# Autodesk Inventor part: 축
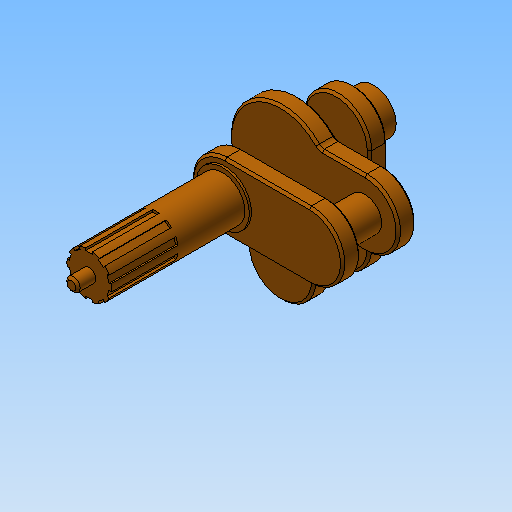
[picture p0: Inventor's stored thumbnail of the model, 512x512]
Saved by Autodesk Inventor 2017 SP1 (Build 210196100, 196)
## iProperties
Created: 2017-05
Part Number: 축
Material: 강철, 연강
Document SubType Name: Modeling
Designer: mduedu
Density: 7.86 g/cm^3
Mass: 656.198 g
Surface Area: 242.498 cm^2
Volume: 83.4857 cm^3
Appearance: 주황색
Author: mduedu
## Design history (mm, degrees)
sketch "스케치1"
  geometry: L1 (-38, 15)-(-17.436, 15); L2 (-38, -15)-(-17.436, -15); L3 (-15, -38)-(-15, -17.436); L4 (15, -38)-(15, -17.436); A1 r 23 centre (0, 0) between (-17.436, 15) and (-17.436, -15); A2 r 15 centre (-38, 0) between (-38, 15) and (-38, -15); A3 r 15 centre (0, -38) between (-15, -38) and (15, -38); 1 further point
  constraints: 8 end point, 8 point on circle, 4 tangent, 3 centre point, 2 horizontal, 2 vertical, 1 coincident, 1 horizontal alignment, 1 vertical alignment
  dimensions: "d0" = 46 diameter of A1; "d1" = 30 diameter of A2; "d2" = 30 diameter of A3 (= d1); "d3" = 38 distance of point (0, 0) A2.centre; "d4" = 38 distance of A3.centre point (0, 0)
extrude "돌출1" new body sketch "스케치1" distance "d5" = 8; taper "d6" = 0 deg
fillet "모깎기1" dims "d7" = 3
sketch "스케치2"
  geometry: C1 r 7.5 at (0, -38); A1 r 15 centre (0, -38) between (-15, -38) and (15, -38) reference; 1 further point
  constraints: 1 centre point, 1 coincident
  dimensions: "d8" = 15 diameter of C1
extrude "돌출2" join sketch "스케치2" distance "d9" = 17; taper "d10" = 0 deg
sketch "스케치3"
  geometry: L1 (-15, 0)-(-15, 38); L2 (15, 0)-(15, 38); C1 r 7.5 at (0, 0) reference; A1 r 15 centre (0, 0) between (-15, 0) and (15, 0); A2 r 15 centre (0, 38) between (-15, 38) and (15, 38); 1 further point
  constraints: 4 end point, 4 point on circle, 4 tangent, 2 centre point, 2 coincident
  dimensions: "d11" = 30 diameter of A1; "d12" = 30 diameter of A2 (= d11)
extrude "돌출3" join sketch "스케치3" distance "d13" = 8; taper "d14" = 0 deg
sketch "스케치4"
  geometry: C1 r 12 at (0, 38); A1 r 15 centre (0, 38) between (15, 38) and (-15, 38) reference; 1 further point
  constraints: 1 centre point, 1 coincident
  dimensions: "d15" = 24 diameter of C1
extrude "돌출4" join sketch "스케치4" distance "d16" = 1; taper "d17" = 0 deg
sketch "스케치5"
  geometry: C1 r 10 at (0, 0); 1 further point
  constraints: 1 centre point, 1 coincident
  dimensions: "d18" = 20 diameter of C1
extrude "돌출5" join sketch "스케치5" distance "d19" = 8; taper "d20" = 0 deg
sketch "스케치6"
  geometry: C1 r 7.5 at (38, 0); A1 r 15 centre (38, 0) between (38, -15) and (38, 15) reference; 1 further point
  constraints: 1 centre point, 1 coincident
  dimensions: "d21" = 15 diameter of C1
extrude "돌출6" join sketch "스케치6" distance "d22" = 17; taper "d23" = 0 deg
sketch "스케치7"
  geometry: L1 (-38, 15)-(0, 15); L2 (-38, -15)-(0, -15); C1 r 7.5 at (0, 0) reference; A1 r 15 centre (0, 0) between (0, 15) and (0, -15); A2 r 15 centre (-38, 0) between (-38, 15) and (-38, -15); 1 further point
  constraints: 4 end point, 4 point on circle, 4 tangent, 2 centre point, 2 coincident
  dimensions: "d24" = 30 diameter of A1; "d25" = 30 diameter of A2 (= d24)
extrude "돌출7" join sketch "스케치7" distance "d26" = 8; taper "d27" = 0 deg
sketch "스케치8"
  geometry: C1 r 12 at (-38, 0); 1 further point
  constraints: 1 centre point, 1 coincident
  dimensions: "d28" = 24 diameter of C1
extrude "돌출8" join sketch "스케치8" distance "d29" = 1; taper "d30" = 0 deg
sketch "스케치9"
  geometry: C1 r 10 at (0, 0); 1 further point
  constraints: 1 centre point, 1 coincident
  dimensions: "d31" = 20 diameter of C1
extrude "돌출9" join sketch "스케치9" distance "d32" = 30; taper "d33" = 0 deg
sketch "스케치10"
  geometry: L1 (1.5, 9.887)-(1.5, 8.887); L2 (1.5, 8.887)-(-1.5, 8.887); L3 (-1.5, 8.887)-(-1.5, 9.887); L4 (-4.598, 8.88)-(-4.01, 8.071); L5 (-4.01, 8.071)-(-6.437, 6.308); L6 (-6.437, 6.308)-(-7.025, 7.117); L7 (-8.939, 4.482)-(-7.988, 4.173); L8 (-7.988, 4.173)-(-8.915, 1.32); L9 (-8.915, 1.32)-(-9.866, 1.629); L10 (-9.866, -1.629)-(-8.915, -1.32); L11 (-8.915, -1.32)-(-7.988, -4.173); L12 (-7.988, -4.173)-(-8.939, -4.482); L13 (-7.025, -7.117)-(-6.437, -6.308); L14 (-6.437, -6.308)-(-4.01, -8.071); L15 (-4.01, -8.071)-(-4.598, -8.88); L16 (-1.5, -9.887)-(-1.5, -8.887); L17 (-1.5, -8.887)-(1.5, -8.887); L18 (1.5, -8.887)-(1.5, -9.887); L19 (4.598, -8.88)-(4.01, -8.071); L20 (4.01, -8.071)-(6.437, -6.308); L21 (6.437, -6.308)-(7.025, -7.117); L22 (8.939, -4.482)-(7.988, -4.173); L23 (7.988, -4.173)-(8.915, -1.32); L24 (8.915, -1.32)-(9.866, -1.629); L25 (9.866, 1.629)-(8.915, 1.32); L26 (8.915, 1.32)-(7.988, 4.173); L27 (7.988, 4.173)-(8.939, 4.482); L28 (7.025, 7.117)-(6.437, 6.308); L29 (6.437, 6.308)-(4.01, 8.071); L30 (4.01, 8.071)-(4.598, 8.88); A1 r 10 centre (0, 0) between (1.5, 9.887) and (-1.5, 9.887); A2 r 10 centre (0, 0) between (-4.598, 8.88) and (-7.025, 7.117); A3 r 10 centre (0, 0) between (-8.939, 4.482) and (-9.866, 1.629); A4 r 10 centre (0, 0) between (-9.866, -1.629) and (-8.939, -4.482); A5 r 10 centre (0, 0) between (-7.025, -7.117) and (-4.598, -8.88); A6 r 10 centre (0, 0) between (-1.5, -9.887) and (1.5, -9.887); A7 r 10 centre (0, 0) between (4.598, -8.88) and (7.025, -7.117); A8 r 10 centre (0, 0) between (8.939, -4.482) and (9.866, -1.629); A9 r 10 centre (0, 0) between (9.866, 1.629) and (8.939, 4.482); A10 r 10 centre (0, 0) between (7.025, 7.117) and (4.598, 8.88); 13 further points
  constraints: 60 end point, 20 point on circle, 10 centre point, 3 coincident, 1 horizontal, 1 midpoint, 1 parallel, 1 vertical, 1 vertical alignment, 103 other
  dimensions: "d37" = 3 distance of L1.end L2.end; "d39" = 1 distance of L2.end L3.end; "d42" = 360 deg dimension on A1.centre L1.start (derived)
extrude "돌출10" join sketch "스케치10" distance "d44" = 30; taper "d45" = 0 deg
sketch "스케치11"
  geometry: C1 r 3 at (0, 0); 1 further point
  constraints: 1 centre point, 1 coincident
  dimensions: "d49" = 6 diameter of C1
extrude "돌출11" join sketch "스케치11" distance "d50" = 8; taper "d51" = 0 deg
chamfer "모따기1" distance "d46" = 1; stored, may be unused: second distance "d47" = 2, angle "d48" = 45 deg
node "솔리드1"
node "투영된 루프1"
node "투영된 루프2"
node "투영된 루프3"
